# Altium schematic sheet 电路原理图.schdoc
size 419 x 297 mm
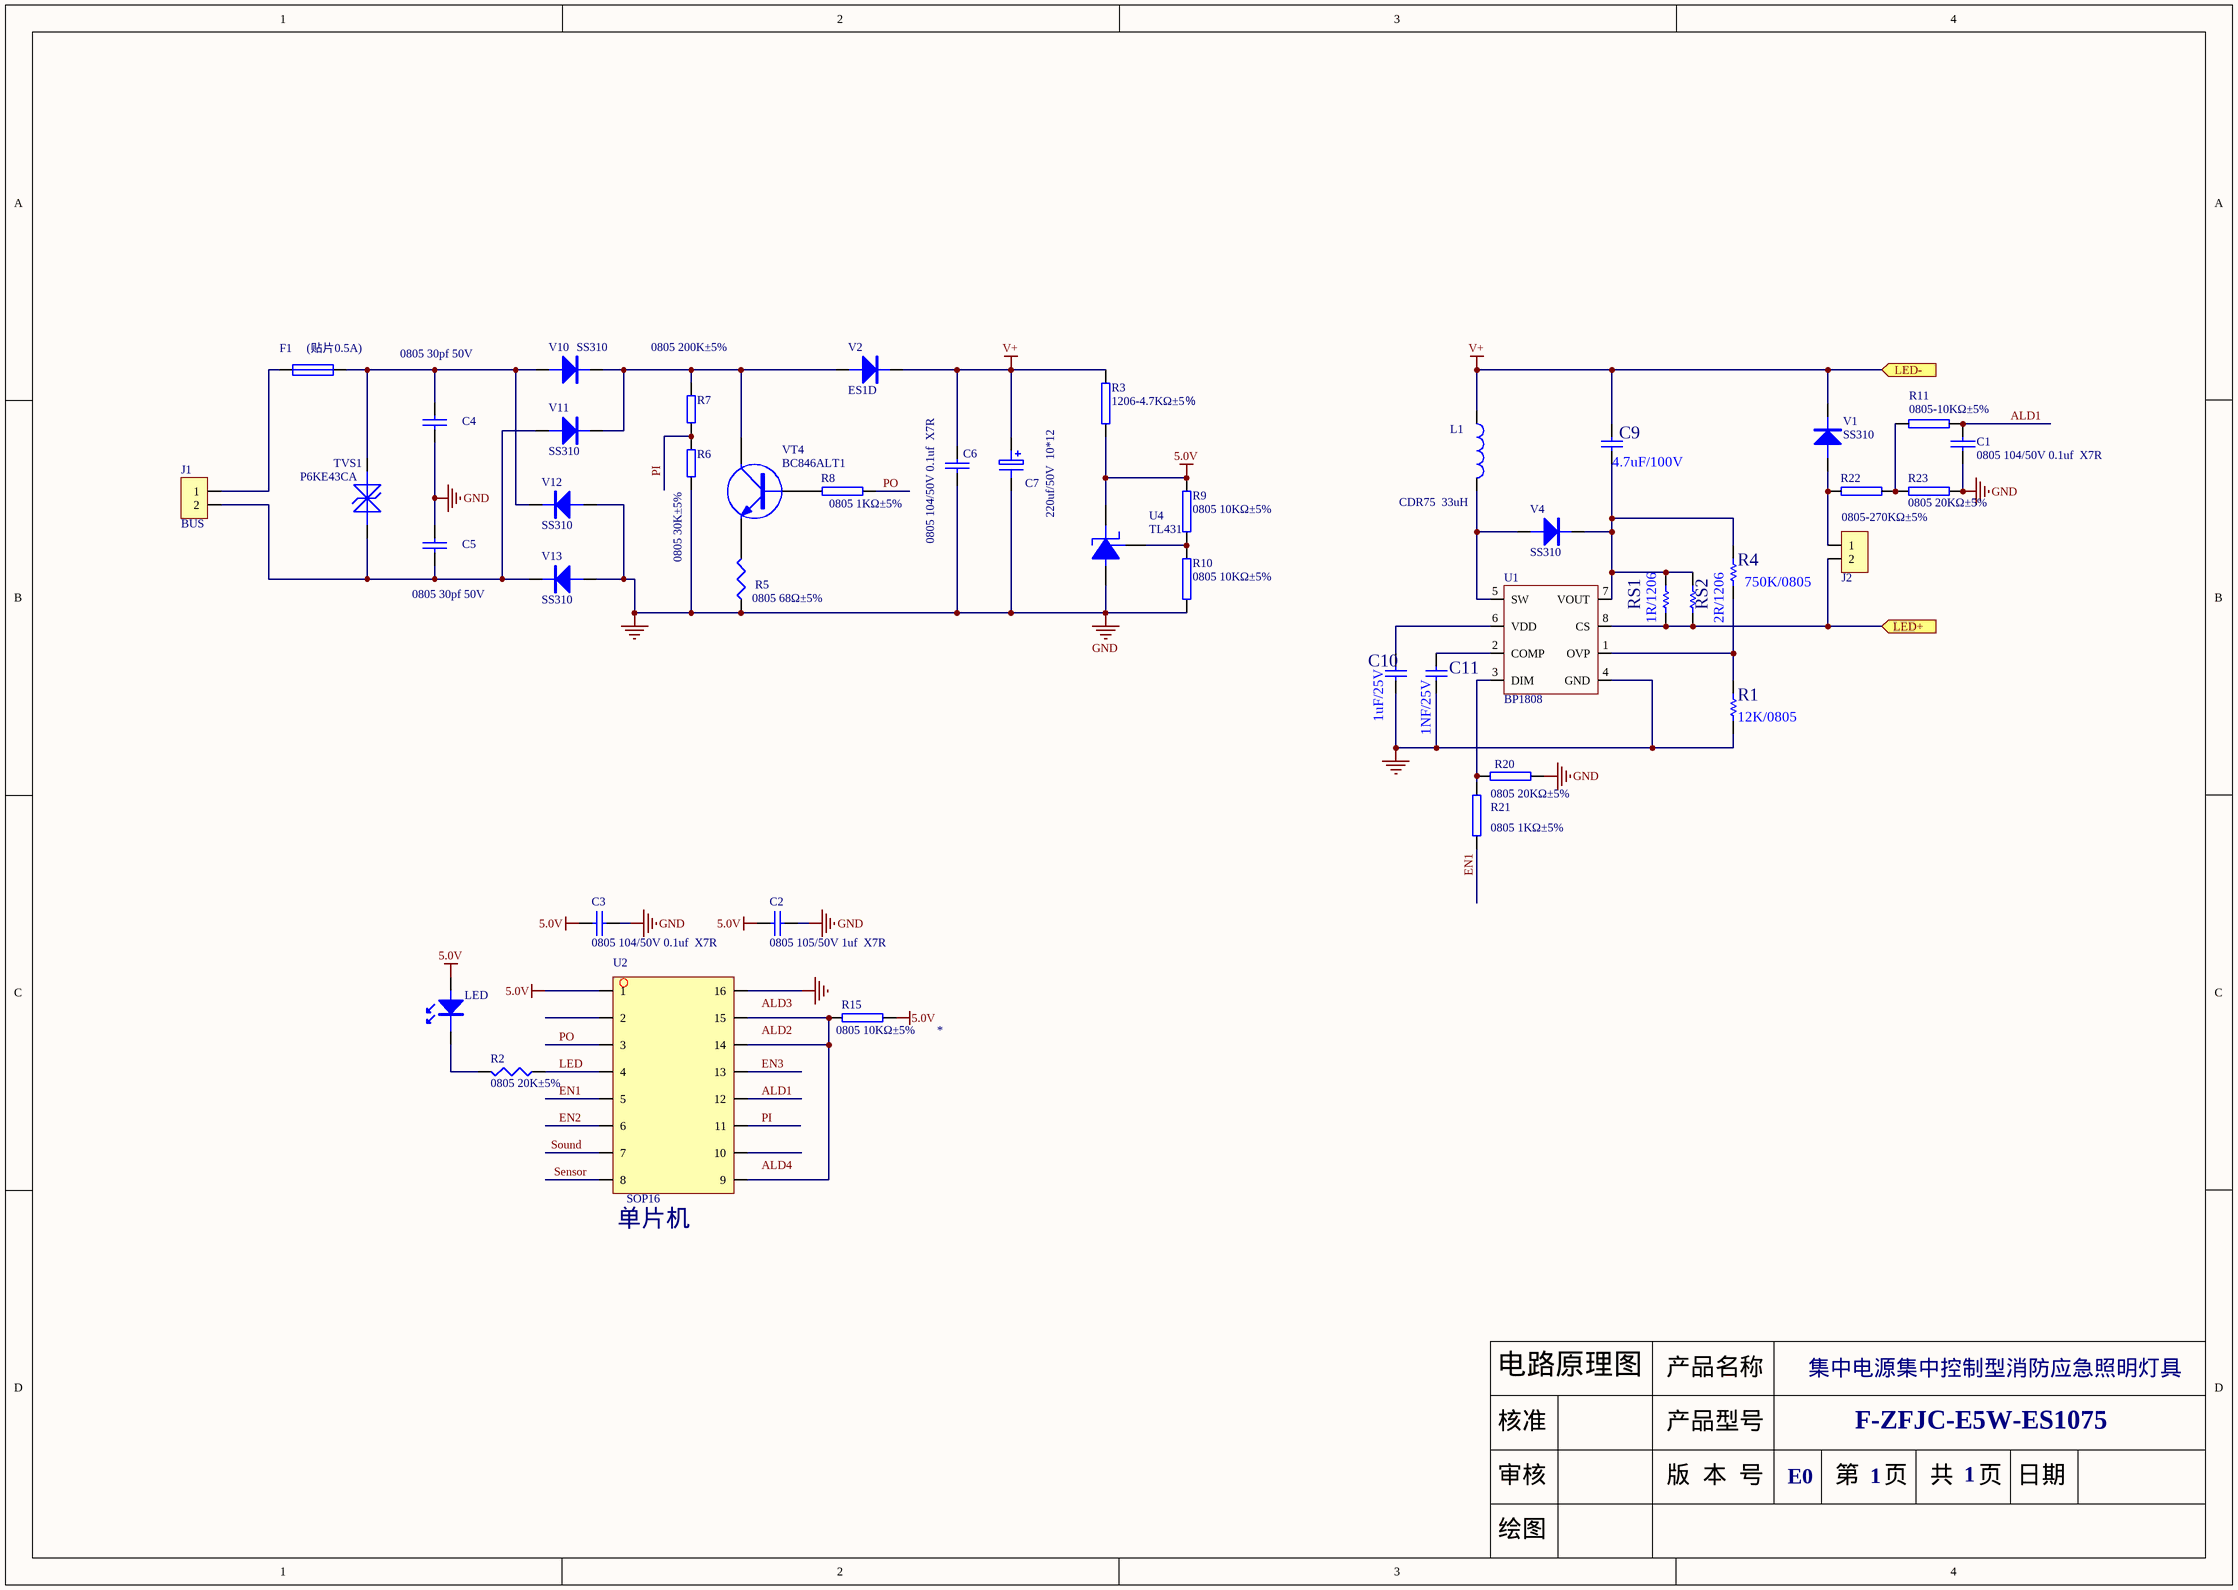
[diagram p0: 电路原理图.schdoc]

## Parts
C1  0805 104/50V 0.1uf  X7R  [0805-c]
C2  0805 105/50V 1uf  X7R  [0805-c]
C3  0805 104/50V 0.1uf  X7R  [0805-c]
C4  0805 30pf 50V  [0805-c]
C5  0805 30pf 50V  [0805-c]
C6  0805 104/50V 0.1uf  X7R  [0805-c]
C7  220uf/50V  10*12  [CE10]
C9  4.7uF/100V  [1206]
C10  1uF/25V  [0805-c]
C11  1NF/25V  [0805-c]
F1  (贴片0.5A)  [贴片保险]
J1  BUS  [TJC-2]
J2  BUS  [tjc-2]  (value not drawn)
L1  CDR75  33uH  [L8]
LED  (no value)  [led0805]
R1  12K/0805  [0805]
R2  0805 20K±5%  [0805]
R3  1206-4.7KΩ±5％  [1206]
R4  750K/0805  [0805]
R5  0805 68Ω±5%  [0805]
R6  0805 30K±5%  [0805]
R7  0805 200K±5%  [0805]
R8  0805 1KΩ±5%  [0805]
R9  0805 10KΩ±5%  [0805]
R10  0805 10KΩ±5%  [0805]
R11  0805-10KΩ±5%  [0805]
R15  0805 10KΩ±5%  [0805]
R20  0805 20KΩ±5%  [0805]
R21  0805 1KΩ±5%  [0805]
R22  0805-270KΩ±5%  [0805]
R23  0805 20KΩ±5%  [0805]
RS1  1R/1206  [1206]
RS2  2R/1206  [1206]
TVS1  P6KE43CA  [SMT_TVS]
U1  BP1808  [sop-8-pp]
U2  SOP16  [SOP-16b]
U4  TL431  [SOT23-A2]
V1  SS310  [VDM7]
V2  ES1D  [DO-214AC]
V4  SS310  [VDM7]
V10  SS310  [VDM7]
V11  SS310  [VDM7]
V12  SS310  [VDM7]
V13  SS310  [VDM7]
VT4  BC846ALT1  [SOT-23]

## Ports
LED+, LED-

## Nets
5.0V: C2.1 C3.1 LED.A R3.2 R9.2 R15.1 U2.1 U4.2
GND: C1.2 C2.2 C3.2 C4.2 C5.1 C6.2 C7.2 C10.1 C11.1 R1.1 R5.1 R6.1 R10.1 R20.1 R23.1 U1.4(GND) U2.16 U4.3 V12.A V13.A
V+: C6.1 C7.1 C9.2 L1.1 R3.1 V1.K V2.K ; port LED-
ALD1: C1.1 R11.1 U2.12
EN1: R21.1 U2.5
EN2: U2.6
EN3: U2.13
LED: R2.1 U2.4
LED+: J2.2 RS1.2 RS2.2 U1.8(CS) ; port LED+
PI: R6.2 R7.1 U2.11
PO: R8.2 U2.3
Sensor: U2.8
Sound: U2.7
NetC4_1: C4.1 F1.2 TVS1.A V10.A V12.K
NetC5_2: C5.2 J1.2 TVS1.K V11.A V13.K
NetC9_1: C9.1 R4.2 RS1.1 RS2.1 U1.7(VOUT) V4.K
NetC10_2: C10.2 U1.6(VDD)
NetC11_2: C11.2 U1.2(COMP)
NetF1_1: F1.1 J1.1
NetJ2_1: J2.1 R22.2 V1.A
NetL1_2: L1.2 U1.5(SW) V4.A
NetLED_K: LED.K R2.2
NetR1_2: R1.2 R4.1 U1.1(OVP)
NetR5_2: R5.2 VT4.2(E)
NetR7_2: R7.2 V2.A V10.K V11.K VT4.3(C)
NetR8_1: R8.1 VT4.1(B)
NetR9_1: R9.1 R10.2 U4.1
NetR11_2: R11.2 R22.1 R23.2
NetR15_2: R15.2 U2.9 U2.14 U2.15
NetR20_2: R20.2 R21.2 U1.3(DIM)

Not connected (* = marked no-connect by the designer): U2 2 10

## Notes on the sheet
- (near U2) 单片机
- 集中电源集中控制型消防应急照明灯具
- F-ZFJC-E5W-ES1075
- E0
- 1
- Labels drawn without touching a wire or pin: ALD2, ALD3, ALD4

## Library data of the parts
C1-C3 C6 = CAP: 料号: 4.1.CTX.004; 型号规格: 104/50V ±10% X7R 5000H RoHS; 名称: 0603封装贴片电容
C4 C5 = CAP: 料号: 4.1.CTX.054; 型号规格: 30PF/50V ±10% X7R 5000H RoHS; 名称: 0603封装贴片电容
C7 = ELECTRO1: 料号: 4.1.C.113; 型号规格: 330UF/50V 10*16 105℃ 误差±20% 5000-10000H 脚长(3.2-3.5mm); 名称: 电解电容
C9-C11 = Cap: Capacitor
F1 = FUSE1: 料号: 4.3.X.111; 型号规格: 仓 24F系列 快断保险管 2A250V; 名称: 贴片保险管
J1 = CON2
J2 = CON2: 新料: 无
L1 = INDUCTOR: 料号: 4.5.LG.151; 型号规格: CD54-100uH; 名称: 贴片电感
LED = LED: 料号: 4.3.LED.250; 名称: 发光二极管; 型号规格: C0805UG-ES 高亮白发绿贴片 VF:2.8-3.0 IV:250-300 WLD:515-520  IF:30MA
R1 R4 RS1 RS2 = Res1: Resistor
R2 = RES1: 料号: 4.2.RTD.246; 型号规格: 15R(15Ω) ±1%RoHS; 名称: 0805封装贴片电阻
R3 = RES2
R5 = RES1: 料号: 4.2.RTD.244; 型号规格: 680(68Ω) ±5%; 名称: 0805封装贴片电阻
R6 = RES: 料号: 4.2.RTD.044; 型号规格: 203(20KΩ) ±5%; 名称: 0805封装贴片电阻
R7 = RES: 料号: 4.2.RTD.130; 型号规格: 274(270KΩ) ±5%; 名称: 0805封装贴片电阻
R8-R10 R15 R21 = RES2: 料号: 4.2.RTX.002; 型号规格: 102(1KΩ) ±5%; 名称: 0603封装贴片电阻
R11 R22 = RES1: 料号: 4.2.RTX.009; 型号规格: 204(200KΩ) ±5%; 名称: 0603封装贴片电阻
R20 = RES2: 料号: 4.2.RTX.003; 型号规格: 103(10KΩ) ±5%; 名称: 0603封装贴片电阻
R23 = RES2: 料号: 4.2.RTX.035A; 型号规格: 203(20KΩ) ±1%; 名称: 0603封装贴片电阻
TVS1 = TVS1: 料号: 4.3.DT.064; 型号规格: 瞬态二极管 P6KE43CA  SMT_TVS; 名称: 贴片瞬态二极管
V1 V4 V10-V13 = DIODE: pin to pad: A>1 K>2; 料号: 4.3.DT.065; 型号规格: SS310 SMA 3A/100V  RoHS; 名称: 贴片肖特基二极
V2 = DIODE: 料号: 4.3.D.033; 型号规格: ES1D 1A/200V SMA -55~125℃ RoHS，编带; 名称: 贴片超快恢复二极管
VT4 = NPN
